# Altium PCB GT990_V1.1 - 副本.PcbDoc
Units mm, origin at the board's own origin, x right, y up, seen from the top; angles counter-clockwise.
Board outline 120.5 x 74 mm, 2 copper layers (Top Layer, Bottom Layer); 143 components, 117 nets, 494 pads, 147 vias.
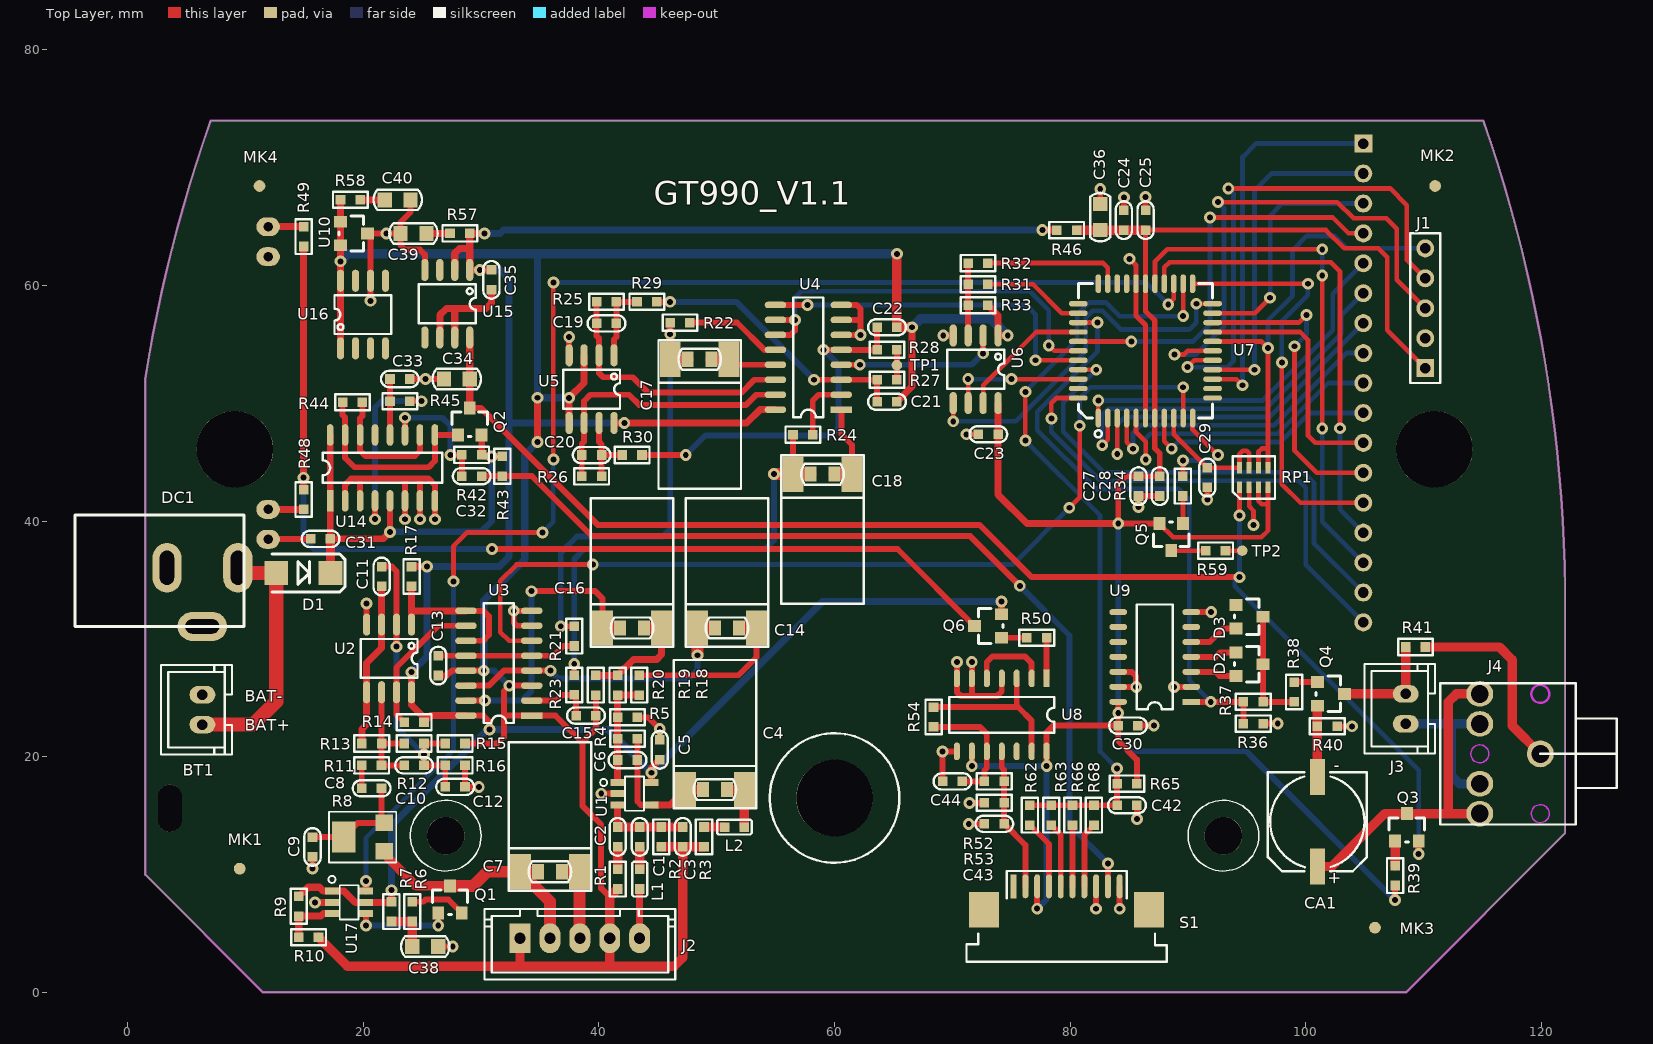
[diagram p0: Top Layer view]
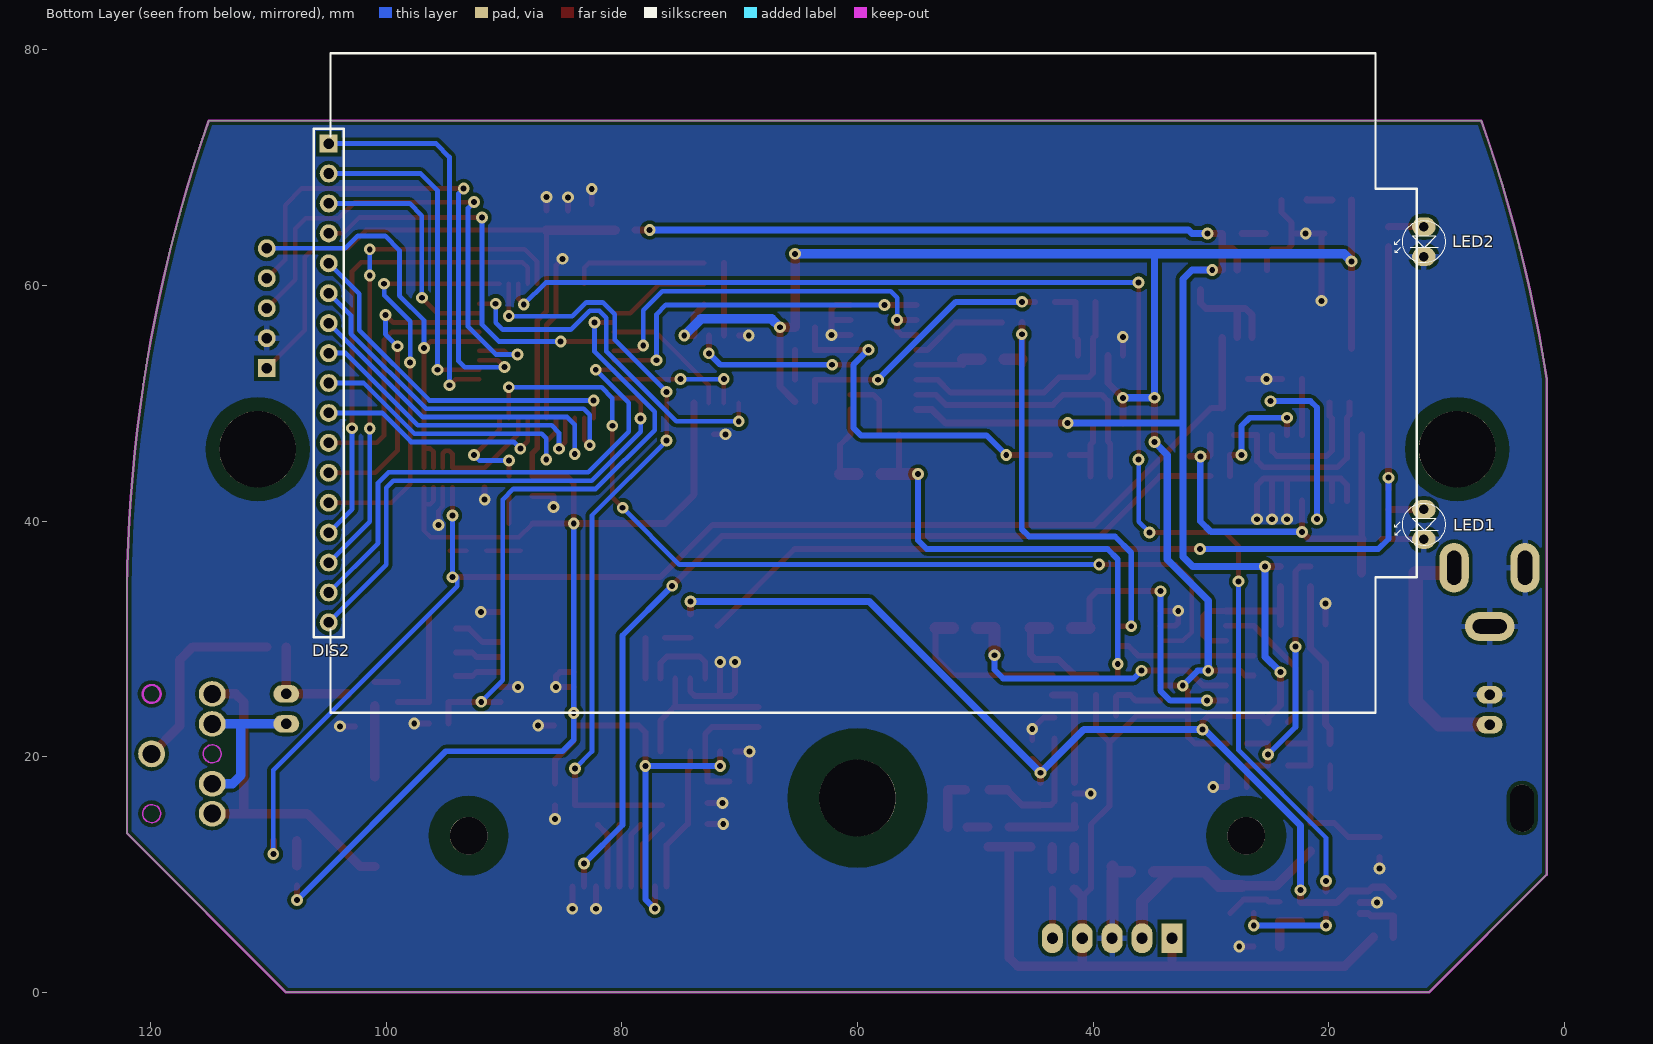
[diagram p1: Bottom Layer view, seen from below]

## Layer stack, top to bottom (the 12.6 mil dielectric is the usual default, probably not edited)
Top Solder: solder mask 0.0102, Solder Resist, Dk 3.5
Top Layer: signal copper 0.0356
Dielectric 1: dielectric 0.32, FR-4, Dk 4.8
Bottom Layer: signal copper 0.0356
Bottom Solder: solder mask 0.0102, Solder Resist, Dk 3.5

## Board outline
1.501,9.999 1.501,52.065 cw(c123.242,32.89) 7.057,73.996 7.045,74 115.06,74 115.061,74 cw(c-3.242,32.868) 122,34.303 122,13.5 108.5,0 11.5,0

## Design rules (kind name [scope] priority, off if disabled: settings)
Clearance [All] p1: gap=0.305
PolygonConnect ISVIA [ISVIA] p1: connectstyle=Direct reliefconductorwidth=0.254 reliefentries=4 polygonreliefangle="90 Angle" airgapwidth=0.254
PolygonConnect [All] p2: connectstyle=Relief reliefconductorwidth=0.5 reliefentries=4 polygonreliefangle="90 Angle" airgapwidth=0.305
RoutingVias [All] p1: holewidth=0.5 width=1.27 viastyle="Through Hole" minholewidth=0.3 minwidth=1 maxholewidth=1 maxwidth=1.27
SolderMaskExpansion [All] p1: expansion=0.102
Width [All] p1: maxlimit=1.5 minlimit=0.2 preferedwidth=0.254
30 further rules are at their usual default settings.

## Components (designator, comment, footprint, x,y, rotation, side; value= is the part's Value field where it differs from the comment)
BT1 "Battery" XH2.54-2P-D 6.349,23.993 r90 top
C1 "47nF" C0603 43.462,13.2 r270 top
C2 "1nF" C0603 41.59,13.2 r90 top
C3 "330pF" C0603 47.113,13.2 r90 top
C4 "u47J63V" CL-P5&SMD-W 49.844,17.216 r0 top
C5 "220nF" C0603 45.163,20.594 r270 top
C6 "2.2nF" C0603 42.43,19.723 r180 top
C7 "u47J63V" CL-P5&SMD-W 35.845,10.239 r0 top
C8 "220nF" C0603 20.71,17.318 r180 top
C9 "10nF" C0603 15.694,12.347 r270 top
C10 "10nF" C0603 24.314,19.268 r180 top
C11 "2.2nF" C0603 21.557,35.298 r270 top
C12 "220nF" C0603 27.799,17.44 r0 top
C13 "470nF" C0603 26.362,27.737 r90 top
C14 "1uJ63V" CL-P5&SMD-W 50.871,30.93 r0 top
C15 "470nF" C0603 38.903,23.495 r180 top
C16 "1uJ63V" CL-P5&SMD-W 42.813,30.93 r0 top
C17 "u47J63V" CL-P5&SMD-W 48.554,53.749 r180 top
C18 "u47J63V" CL-P5&SMD-W 58.978,43.99 r180 top
C19 "3.3nF" C0603 40.649,56.782 r0 top
C20 "3.3nF" C0603 39.387,45.608 r0 top
C21 "1uF" C0603 64.455,50.135 r0 top
C22 "1uF" C0603 64.455,56.451 r0 top
C23 "1uF" C0603 73.049,47.366 r180 top
C24 "220nF" C0603 84.559,65.537 r90 top
C25 "220nF" C0603 86.396,65.537 r90 top
C27 "220nF" C0603 85.799,42.967 r270 top
C28 "220nF" C0603 87.592,42.967 r270 top
C29 "220nF" C0603 91.639,43.701 r270 top
C30 "220nF" C0603 84.914,22.644 r0 top
C31 "1uF" C0603 16.378,38.489 r180 top
C32 "220nF" C0603 29.202,43.815 r180 top
C33 "220nF" C0603 23.108,52.06 r0 top
C34 "10uF/16V" C0805 27.937,52.062 r0 top
C35 "10nF" C0603 30.881,60.48 r270 top
C36 "10uF/16V" C0805 82.553,65.799 r270 top
C38 "10uF/16V" C0805 25.262,3.891 r180 top
C39 "10uF/16V" C0805 24.263,64.419 r0 top
C40 "10uF/16V" C0805 22.924,67.273 r180 top
C42 "100nF" C0603 84.822,15.88 r180 top
C43 "100nF" C0603 73.56,14.3 r180 top
C44 "100nF" C0603 70.007,17.904 r180 top
CA1 "470uF/16V" SMD-D8X10.5MM 100.98,14.485 r90 top
D1 "SS14" SMA 14.919,35.598 r0 top
D2 "BAT54A" SOT-23 95.227,27.854 r270 top
D3 "BAT54A" SOT-23 95.227,31.887 r270 top
DC1 "DC005" DC005 6.351,33.547 r180 top
DIS2 "LCD" DIP17-2.54 104.875,51.721 r270 bottom
J1 "NC" DIP5-2.54 110.134,58.067 r90 top
J2 "XH2.54-5P" XH2.54-5P-D 38.382,4.592 r0 top
J3 "XH2.54-2P" XH2.54-2P-D 108.473,24.066 r90 top
J4 "PJ-306" PJ-306 117.331,20.25 r270 top
L1 "27uH" L0603 43.462,9.611 r270 top
L2 "27uH" L0603 51.506,14.034 r180 top
LED1 "LED" LED-3MM-CLEAR 11.927,39.722 r270 bottom
LED2 "LED" LED-3MM-CLEAR 11.927,63.717 r270 bottom
MK1 "" MARK 9.509,10.503 r0 top
MK2 "" MARK 110.975,68.443 r0 top
MK3 "" MARK 105.867,5.491 r0 top
MK4 "" MARK 11.194,68.443 r0 top
Q1 "MMBT4403LT1G" SOT-23 27.361,7.89 r0 top
Q2 "ZXMP3A13FTA" SOT-23 29.038,48.465 r0 top
Q3 "FMMT591ATA" SOT-23 108.576,14.019 r0 top
Q4 "ZXMN3A01FTA" SOT-23 102.131,25.336 r270 top
Q5 "MMBT4403LT1G" SOT-23 88.57,38.646 r180 top
Q6 "S9012" SOT-23 73.018,31.102 r90 top
R1 "4.99K/1%" R0603 41.59,9.611 r90 top
R2 "30.1K/1%" R0603 45.301,13.2 r90 top
R3 "49.9R/1%" R0603 48.918,13.2 r90 top
R4 "30.1K/1%" R0603 42.43,21.539 r180 top
R5 "10K" R0603 42.43,23.348 r0 top
R6 "10R" R0603 24.163,6.852 r90 top
R7 "10R" R0603 22.394,6.853 r270 top
R8 "500R" SMD-3X3MM 20.066,13.186 r90 top
R9 "453R/1%" R0603 14.524,7.308 r90 top
R10 "499R/1%" R0603 15.363,4.674 r180 top
R11 "6.04K/1%" R0603 20.713,19.263 r0 top
R12 "28K/1%" R0603 24.314,21.123 r0 top
R13 "10K" R0603 20.718,21.123 r0 top
R14 "10K" R0603 24.314,22.926 r180 top
R15 "10K" R0603 27.799,21.123 r180 top
R16 "20K" R0603 27.799,19.268 r180 top
R17 "10K" R0603 24.097,35.298 r270 top
R18 "4.99K/1%" R0603 43.428,26.076 r90 top
R19 "40.2K/1%" R0603 41.584,26.076 r90 top
R20 "5.76K/1%" R0603 39.74,26.073 r90 top
R21 "10K" R0603 37.903,30.236 r90 top
R22 "274K/1%" R0603 46.886,56.85 r0 top
R23 "10K" R0603 37.903,26.083 r90 top
R24 "274K/1%" R0603 57.311,47.341 r0 top
R25 "2.21M/1%" R0603 40.652,58.61 r0 top
R26 "2.21M/1%" R0603 39.387,43.792 r0 top
R27 "20K" R0603 64.455,51.996 r0 top
R28 "100K" R0603 64.455,54.536 r0 top
R29 "2K" R0603 44.073,58.61 r0 top
R30 "2K" R0603 42.818,45.611 r0 top
R31 "162K/1%" R0603 72.178,60.094 r0 top
R32 "64.9K/1%" R0603 72.178,61.9 r0 top
R33 "10R" R0603 72.178,58.323 r0 top
R34 "20K" R0603 89.571,42.967 r270 top
R36 "100K" R0603 95.54,22.814 r180 top
R37 "10K" R0603 95.54,24.661 r180 top
R38 "49.9K/1%" R0603 99.002,25.499 r270 top
R39 "4.99K/1%" R0603 107.575,9.909 r90 top
R40 "0R" R0603 101.818,22.583 r0 top
R41 "274R/1%" R0603 109.308,29.314 r0 top
R42 "499K/1%" R0603 29.202,45.621 r0 top
R43 "20K" R0603 31.811,44.653 r90 top
R44 "20K" R0603 19.084,50.089 r180 top
R45 "1M" R0603 23.108,50.18 r0 top
R46 "4.99R/1%" R0603 79.703,64.699 r0 top
R48 "100R" R0603 14.934,41.831 r90 top
R49 "100R" R0603 14.934,64.148 r270 top
R50 "1K" R0603 77.164,30.104 r0 top
R52 "10K" R0603 73.557,17.907 r180 top
R53 "5.1K" R0603 73.557,16.086 r0 top
R54 "1M" R0603 68.401,23.378 r90 top
R57 "0.47R/1%" R0603 28.199,64.419 r0 top
R58 "0.47R/1%" R0603 18.908,67.27 r0 top
R59 "49.9R/1%" R0603 92.342,37.495 r180 top
R62 "4.53K/1%" R0603 76.582,15.042 r270 top
R63 "2.32K/1%" R0603 78.391,15.042 r270 top
R65 "10K" R0603 84.822,17.724 r180 top
R66 "12.7K/1%" R0603 80.197,15.042 r270 top
R68 "7.68K/1%" R0603 82.018,15.042 r270 top
RP1 "22K" RP0603 95.583,43.701 r0 top
S1 "FPC-1.0MM-10P-UP" FPC-1.0MM-10P 79.699,8 r0 top
TP1 "" TP35 65.293,53.241 r0 top
TP2 "" TP35 94.607,37.495 r90 top
U1 "TS971ILT" SOT-23-5 43.026,16.868 r270 top
U2 "LM393DR" SOP8 22.191,28.344 r180 top
U3 "74HC4053D" SOP16 31.51,27.94 r180 top
U4 "74HC4053D" SOP16 57.78,53.901 r180 top
U5 "TLC2262AIDR" SOP8 39.382,51.201 r180 top
U6 "MCP3301-CI/SN" SOP8 71.977,52.885 r180 top
U7 "PIC16F1939-I/PT" TQFP44 86.389,54.45 r0 top
U8 "MC14013BDG" SOP14 74.192,23.557 r270 top
U9 "SN74HC393DR" SOP14 87.175,28.471 r180 top
U10 "NC/TL431ACDBZR" SOT-23 19.217,64.409 r270 top
U14 "74HC4053D" SOP16 21.635,44.516 r90 top
U15 "LP2951ACMC" SOP8 27.132,58.448 r180 top
U16 "TL431ACDR" SOP8 19.974,57.532 r0 top
U17 "TS5A3157DBVR" SOT-23-6 18.798,7.64 r270 top

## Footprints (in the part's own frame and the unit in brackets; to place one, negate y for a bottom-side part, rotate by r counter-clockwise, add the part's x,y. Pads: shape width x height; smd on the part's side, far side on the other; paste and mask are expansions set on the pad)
C0603 [mil]
  rect 32x32 smd: 1(-33,0) 2(33,0)
  silkscreen extent -63,-27 63,27, body extent -31,-16 32,16, height 20
C0805 [mm]
  rect 1.2x1.27 smd: 1(-1.1,0) 2(1.1,0)
  silkscreen extent -2.06,-0.86 2.06,0.86, body extent -1,-0.62 1,0.63, height 0.8
CL-P5&SMD-W [mm]
  rect 1.778x3 smd: 1(-2.5,0) 2(2.5,0)
  rect 1.016x1.3 smd: 1(-1.016,0) 2(1.016,0)
  silkscreen extent -3.5,-1.6 3.5,11
DC005 [mil]
  oval 98x165 hole 47.24 slot 114 at 90 deg: 1(-118.5,-98) 3(118.5,-98)
  oval 165x98 hole 47.24 slot 114 at 0 deg: 2(0.5,98)
  silkscreen extent -138,-275 426,98, body extent -146,-270 420,100, height 437
DIP5-2.54 [mil]
  rect 60x60 hole 35.43: 1(-200,0)
  round 60 hole 35.43: 2(-100,0) 3(0,0) 4(100,0) 5(200,0)
  silkscreen extent -250,-50 250,50, body extent -250,-50 250,50, height 336
DIP17-2.54 [mil]
  rect 60x60 hole 35.43: 1(-800,0)
  round 60 hole 35.43: 2(-700,0) 3(-600,0) 4(-500,0) 5(-400,0) 6(-300,0) 7(-200,0) 8(-100,0) 9(0,0) 10(100,0) 11(200,0) 12(300,0) 13(400,0) 14(500,0) 15(600,0) 16(700,0) 17(800,0)
  silkscreen extent -850,-50 850,50, body extent -851,-50 850,51, height 336
FPC-1.0MM-10P [mm]
  rect 0.508x2.032 smd mask+0.025: 1(-4.5,1)
  oval 0.508x2.032 smd mask+0.025: 2(-3.5,1) 3(-2.5,1) 4(-1.5,1) 5(-0.5,1) 6(0.5,1) 7(1.5,1) 8(2.5,1) 9(3.5,1) 10(4.5,1)
  rect 2.54x3 smd mask+0.025: 11(-7,-1) 12(7,-1)
  silkscreen extent -8.5,-5.4 8.5,2.3, body extent -7.9,-5.07 7.9,1.43, height 2.7
L0603 [mm]
  rect 0.813x0.813 smd: 1(-0.838,0) 2(0.838,0)
  silkscreen extent -1.47,-0.64 1.47,0.64, body extent -0.8,-0.4 0.8,0.4, height 0.4
LED-3MM-CLEAR [mm]
  oval 1.6x2 hole 0.8: 1(-1.27,0) 2(1.27,0)
  silkscreen extent -1.8,-2.48 1.8,1.8, body extent -1.9,-1.9 1.53,1.9, height 10.64
MARK [mm]
  round 1 smd mask+1: 1(0,0)
  Top Layer pour cut-out: -1.5,0 -1.351,-0.651 -0.935,-1.173 -0.334,-1.462 0.334,-1.462 0.935,-1.173 1.351,-0.651 1.5,0 1.5,0 1.5,-0.003 1.351,0.648 0.935,1.17 0.334,1.46 -0.334,1.46 -0.935,1.17 -1.351,0.648 -1.5,-0.003 -1.5,-0.003
PJ-306 [mil]
  round 90 hole 60 mask+4: 1(0,101.15)
  oval 85x90 hole 60 mask+4: 2(200,-101.15) 3(100,-101.15) 4(-100,-101.15) 5(-200,-101.15)
  Keep-Out Layer circle w5: c200,101.15 r30
  Keep-Out Layer circle w7.87: c-200,101.15 r30
  Keep-Out Layer circle w5: c0,-101.15 r30
  silkscreen extent -236,-233 236,357, body extent -236,-240 236,354, height 394
R0603 [mil]
  rect 32x32 smd: 1(-33,0) 2(33,0)
  silkscreen extent -58,-27 58,27, body extent -31,-16 32,16, height 18
RP0603 [mil]
  rect 17x38 smd: 1(-47.5,-33) 2(-15.5,-33) 3(15.5,-33) 4(47.5,-32.99) 5(47.5,32.99) 6(15.5,33) 7(-15.5,33) 8(-47.5,32.99)
  silkscreen extent -71,-71 71,71, body extent -63,-31 63,31, height 20
SMA [mm]
  rect 2x2 smd: 1(-2.3,0) 2(2.3,0)
  silkscreen extent -2.68,-1.6 3.55,1.6, body extent -2.3,-1.35 2.3,1.35, height 2.4
SMD-3X3MM [mm]
  rect 1.4x1.5 smd: 1(-1.199,-1.725) 2(1.199,-1.724)
  rect 2.6x2 smd: 3(-0.001,1.725)
  silkscreen extent -2.15,-2.73 2.15,2.97, body extent -1.9,-2.11 1.9,2.39, height 1.01
SMD-D8X10.5MM [mm]
  rect 3.048x1.27 smd mask+0.025: 1(-3.8,0) 2(3.8,0)
  silkscreen extent -4.2,-4.2 4.2,4.2, body extent -4.95,-4.15 4.95,4.15, height 10.2
SOP8 [mil]
  oval 24x74 smd: 1(-75,-113) 2(-25,-113) 3(25,-113) 4(75,-113) 5(75,113) 6(25,113) 7(-25,113) 8(-75,113)
  silkscreen extent -95,-65 95,65, body extent -96,-118 96,118, height 67
SOP14 [mm]
  rect 1.5x0.51 smd: 1(-3.1,3.81)
  oval 1.5x0.51 smd: 2(-3.1,2.54) 3(-3.1,1.27) 4(-3.1,0) 5(-3.1,-1.27) 6(-3.1,-2.54) 7(-3.1,-3.81) 8(3.1,-3.81) 9(3.1,-2.54) 10(3.1,-1.27) 11(3.1,0) 12(3.1,1.27) 13(3.1,2.54) 14(3.1,3.81)
  silkscreen extent -1.52,-4.44 1.52,4.44, body extent -3.1,-4.35 3.1,4.35, height 1.61
SOP16 [mil]
  rect 72x22 smd: 1(-110,175)
  oval 72x22 smd: 2(-110,125) 3(-110,75) 4(-110,25) 5(-110,-25) 6(-110,-75) 7(-110,-125) 8(-110,-175) 9(110,-175) 10(110,-125) 11(110,-75) 12(110,-25) 13(110,25) 14(110,75) 15(110,125) 16(110,175)
  silkscreen extent -50,-200 50,200, body extent -123,-196 123,196, height 62
SOT-23 [mm]
  rect 1x1.1 smd: 1(-1,-1.15) 2(1,-1.15) 3(0,1.15)
  silkscreen extent -1.5,-1.27 1.5,0.8, body extent -1.45,-1.4 1.45,1.4, height 1.2
SOT-23-5 [mm]
  rect 0.6x1.2 smd: 1(-0.95,-1.435) 2(0,-1.435) 3(0.95,-1.435) 4(0.95,1.435) 5(-0.95,1.435)
  silkscreen extent -1.45,-2.93 1.45,0.8, body extent -1.45,-1.4 1.45,1.4, height 1.2
SOT-23-6 [mm]
  rect 0.6x1.2 smd: 1(-0.95,-1.435) 2(0,-1.435) 3(0.95,-1.435) 4(0.95,1.435) 5(0,1.435) 6(-0.95,1.435)
  silkscreen extent -2.25,-1.75 1.45,0.8, body extent -1.5,-1.4 1.5,1.4, height 0.86
TP35 [mil]
  round 35 smd: 1(0,0)
TQFP44 [mm]
  oval 0.457x1.6 smd mask+0.025: 1(-4,-5.7) 2(-3.2,-5.7) 3(-2.4,-5.7) 4(-1.6,-5.7) 5(-0.8,-5.7) 6(0,-5.7) 7(0.8,-5.7) 8(1.6,-5.7) 9(2.4,-5.7) 10(3.2,-5.7) 11(4,-5.7) 23(4,5.7) 24(3.2,5.7) 25(2.4,5.7) 26(1.6,5.7) 27(0.8,5.7) 28(0,5.7) 29(-0.8,5.7) 30(-1.6,5.7) 31(-2.4,5.7) 32(-3.2,5.7) 33(-4,5.7)
  oval 1.6x0.457 smd mask+0.025: 12(5.7,-4) 13(5.7,-3.2) 14(5.7,-2.4) 15(5.7,-1.6) 16(5.7,-0.8) 17(5.7,0) 18(5.7,0.8) 19(5.7,1.6) 20(5.7,2.4) 21(5.7,3.2) 22(5.7,4) 34(-5.7,4) 35(-5.7,3.2) 36(-5.7,2.4) 37(-5.7,1.6) 38(-5.7,0.8) 39(-5.7,0) 40(-5.7,-0.8) 41(-5.7,-1.6) 42(-5.7,-2.4) 43(-5.7,-3.2) 44(-5.7,-4)
  silkscreen extent -5.7,-7.34 5.7,5.7, body extent -6.01,-6.01 6.01,6.01, height 1.1
XH2.54-2P-D [mm]
  oval 1.5x2.2 hole 0.9: 1(-1.27,0) 2(1.27,0)
  silkscreen extent -3.8,-2.5 3.8,3.5, body extent -3.7,-2.76 3.7,3.34, height 7
XH2.54-5P-D [mil]
  rect 70x100 hole 37: 1(-200,0)
  oval 70x100 hole 37: 2(-100,0) 3(0,0) 4(100,0) 5(200,0)
  silkscreen extent -318,-138 319,98, body extent -293,-134 293,93, height 276

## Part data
BT1 J3: library part XH2.54-2P-D, "XH-2A 2脚直插 脚距2.5mm"
C1: library part C-47nF-0603, "47nF(473) K 0603"
C2: library part C-1nF-0603, "1nF(102) K 0603 50V"
C3: library part C-330pF-0603, "330pF(331) K 0603"
C4 C7 C17 C18: library part C-470nF-63V-PF, "470nF（474）5% 100V 脚距5mm"
C5 C8 C12 C24 C25 C27 C28 C29 C30 C32 C33: library part C-220nF-0603, "220nF(224) K 0603 25V"
C6 C11: library part C-2.2nF-0603, "2.2nF(222) K 0603"
C9 C10 C35: library part C-10nF-0603, "10nF(103) K 0603"
C13 C15: library part C-470nF-0603, "470nF(474) K 0603 25V"
C14 C16: library part C-1uF-63V-PF, "1uF（105）5% 100V 脚距5mm"
C19 C20: library part C-3.3nF-0603, "3.3nF(332) K 0603"
C21 C22 C23 C31: library part C-1uF-0603, "1uF(105) K 0603 25V"
C34 C36 C38 C39 C40: library part C-10uF-0805-16V, "10uF(106) K 0805 16V"
C42 C43 C44: library part C-100nF-0603, "100nF(104) K 0603"
CA1: library part C-470uF-16V-D8XL10.5MM, "470uF/16V Φ8×10.5"
D1: "SS14 SMA"
D2 D3: "BAT54A SOT-23"
DC1: "DC-005 2mm针全铜"
DIS2: library part "17 HEADER", "显示屏"
J1: library part XH2.54-5P-D
J2: library part XH2.54-5P-D, "XH-4A 5脚直插 脚距2.5mm"
J4: "5脚 PJ-306全铜 双声道3.5mm音频"
L1 L2: library part L-27uH-0603, "27uH 0603"
LED1 LED2: "背光"
MK1 MK2 MK3 MK4: library part MARK, "NC"
Q1 Q5: "MMBT4403LT1G SOT-23"
Q2: "ZXMP3A13FTA SOT-23"
Q3: "FMMT591ATA SOT-23(代号591)"
Q4: "ZXMN3A01FTA SOT-23"
Q6: "S9012 SOT-23（代号2T1）"
R1 R18 R39: library part R-4.99K-0603-1%, "1/16W 1% 4.99KΩ 0603"
R2 R4: library part R-30.1K-0603-1%, "1/16W 1% 30.1KΩ 0603"
R3 R59: library part R-49.9R-0603-1%, "1/16W 1% 49.9Ω 0603"
R5 R13 R14 R15 R17 R21 R23 R37 R52 R65: library part R-10K-0603, "1/16W 5% 10KΩ 0603"
R6 R7 R33: library part R-10R-0603-1%, "1/16W 1% 10Ω 0603"
R8: library part R-500R-SMD-3X3MM, "500Ω 3X3"
R9: library part R-453R-0603-1%, "1/16W 1% 453Ω 0603"
R10: library part R-499R-0603-1%, "1/16W 1% 499Ω 0603"
R11: library part R-6.04K-0603-1%, "1/16W 1% 6.04KΩ 0603"
R12: library part R-28K-0603-1%, "1/16W 1% 28KΩ 0603"
R16 R27 R34 R43 R44: library part R-20K-0603, "1/16W 5% 20KΩ 0603"
R19: library part R-40.2K-0603-1%, "1/16W 1% 40.2KΩ 0603"
R20: library part R-5.76K-0603-1%, "1/16W 1% 5.76KΩ 0603"
R22 R24: library part R-274K-0603-1%, "1/16W 1% 274KΩ 0603"
R25 R26: library part R-2.21M-0603-1%, "1/16W 1% 2.21MΩ 0603"
R28 R36: library part R-100K-0603, "1/16W 5% 100KΩ 0603"
R29 R30: library part R-2K-0603, "1/16W 5% 2KΩ 0603"
R31: library part R-162K-0603-1%, "1/16W 1% 162KΩ 0603"
R32: library part R-64.9K-0603-1%, "1/16W 1% 64.9KΩ 0603"
R38: library part R-49.9K-0603-1%, "1/16W 1% 49.9KΩ 0603"
R40: library part R-0R-0603, "1/16W 5% 0Ω 0603"
R41: library part R-274R-0603-1%, "1/16W 1% 274Ω 0603"
R42: library part R-499K-0603-1%, "1/16W 1% 499KΩ 0603"
R45 R54: library part R-1M-0603, "1/16W 5% 1MΩ 0603"
R46: library part R-4.99R-0603-1%, "1/16W 1% 4.99Ω 0603"
R48 R49: library part R-100R-0603, "1/16W 5% 100Ω 0603"
R50: library part R-1K-0603, "1/16W 5% 1KΩ 0603"
R53: library part R-5.1K-0603, "1/16W 5% 5.1KΩ 0603"
R57 R58: library part R-0.47R-0603-1%, "1/16W 1% 0.47Ω 0603"
R62: library part R-4.53K-0603-1%, "1/16W 1% 4.53KΩ 0603"
R63: library part R-2.32K-0603-1%, "1/16W 1% 2.32KΩ 0603"
R66: library part R-12.7K-0603-1%, "1/16W 1% 12.7KΩ 0603"
R68: library part R-7.68K-0603-1%, "1/16W 1% 7.68KΩ 0603"
RP1: library part R-22K-0603X4, "1/16W 5% 22kΩ 4*0603"
S1: "1.0mm间距抽拉上接 1.0-10P"
TP1 TP2: library part VSRC2, "Voltage Source"
U1: "TS971ILT SOT-23-5"
U2: "LM393DR SOP8"
U3 U4 U14: "74HC4053D SOP16"
U5: "TLC2262AIDR SOP8"
U6: "MCP3301-CI/SN SOP8"
U7: "PIC16F1939-I/PT SOP28"
U8: library part MC14013B, "MC14013BDG SOP14"
U9: "SN74HC393DR SOP14"
U10: library part TL431ACDBZR, "NC"
U15: "LP2951ACMC SOP8"
U16: "TL431ACDR SOP8"
U17: "TS5A3157DBVR SOT-23-6"

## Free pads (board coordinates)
  oval 2x4 hole 2 slot 4 at 90 deg unplated: 1(3.584,15.634)
  round 6.5 hole 6.5 unplated: 1(9.1,46.1) 2(110.9,46.1) 3(60,16.5)
  round 3.2 hole 3.2 unplated: 4(27,13.3) 5(93,13.3)

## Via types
v1: diameter 1, hole 0.5, Top Layer to Bottom Layer, tented both sides, 147 vias

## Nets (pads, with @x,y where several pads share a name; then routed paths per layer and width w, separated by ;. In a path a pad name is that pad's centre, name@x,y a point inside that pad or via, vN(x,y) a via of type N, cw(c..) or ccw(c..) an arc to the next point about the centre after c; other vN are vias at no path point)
BAT: C31.1 D1.2 Q2.2 R42.2 R43.2 U14.1 U14.5 U14.16 | length 37.7
  Top Layer w0.55: U14.16 U14.1 17.19,38.515 C31.1 21.676,38.489 v1(22.27,39.082) U14.5 ; Q2.2 30.038,45.624 R42.2 30.17,45.491 v1(30.894,45.491) R43.2
  Top Layer w0.8: C31.1 17.219,38.486 D1.2
  Bottom Layer w0.55: v1(22.27,39.082) 22.272,39.079 29.988,39.079 30.894,39.985 v1(30.894,45.491)
CLK: J1.4 U7.16 | length 43.9
  Top Layer w0.4: v1(89.967,53.068) 90.549,53.65 U7.16 ; v1@93.422,68.234 107.155,68.234 108.572,66.817 108.572,62.169 J1.4
  Bottom Layer w0.4: v1(89.967,53.068) 93.335,53.068 93.853,53.586 93.853,67.803 v1(93.421,68.235)
DAT: J1.3 U7.17 | length 43.2
  Top Layer w0.4: v1(88.844,54.145) 89.682,54.145 89.987,54.45 U7.17 ; v1(92.537,67.074) 102.671,67.074 104.051,65.694 106.838,65.694 107.714,64.818 107.714,60.488 J1.3
  Bottom Layer w0.4: v1(88.844,54.145) 90.701,54.145 93.045,56.49 93.045,66.566 v1(92.537,67.074)
DOWN: R63.2 S1.5 | length 5.5
  Top Layer w0.5: R63.2 79.199,13.396 S1.5
GND: BT1.2 C5.1 C7.2 C9.2 C12.2 C23.2 C24.2 C25.2 C27.2 C28.2 C29.2 C30.2 C31.2 C33.2 C34.1 C36.1 C38.1 C39.1 C40.1 C42.1 C43.2 C44.2 DC1.2 DC1.3 J1.2 J2.3 LED1.2 LED2.2 R5.2 R16.1 R36.1 R40.2 R53.1 RP1.2 S1.8 S1.10 U1.2 U2.4 U3.7 U3.8 U4.6 U4.7 U4.8 U5.4 U6.4 U7.6 U7.29 U8.4 U8.6 U8.7 U8.8 U9.2 U9.7 U9.12 U9.13 U10.3 U14.2 U14.3 U14.6 U14.7 U14.8 U15.4 U16.6 U17.2 | length 137.1
  Top Layer w0.4: RP1.2 95.189,41.255 95.557,40.886 v1(95.557,39.672)
  Top Layer w0.45: v1(71.204,47.366) C23.2 ; v1(85.044,62.258) 85.589,61.713 U7.29 85.589,57.43 86.389,56.63 U7.6
  Top Layer w0.5: LED1.2 11.963,38.489 C31.2 ; v1(15.694,10.512) C9.2 ; U14.2 18.46,43.09 18.971,43.602 19.69,43.602 ; U14.3 19.73,43.562 19.69,43.602 ; U2.4 v1(20.286,33.011) ; v1(20.609,58.694) U16.6 20.609,64.167 U10.3 v1(21.958,64.409) C39.1@23.153,64.409 ; v1(23.54,40.159) U14.6 23.54,43.6 23.538,43.602 ; C33.2 v1(25.293,52.06) 26.835,52.06 C34.1 ; C40.1 24.024,66.228 23.153,65.358 C39.1@23.153,64.409 ; v1(24.81,40.159) U14.7 24.81,43.59 24.821,43.602 ; U15.4 25.227,62.614 24.803,63.038 23.538,63.038 23.153,63.423 C39.1@23.153,64.409 ; v1(26.08,40.159) U14.8 26.08,43.069 25.547,43.602 24.821,43.602 ; C38.1 v1(27.592,3.891) ; R16.1 C12.2 v1(29.807,17.44) ; U3.7 33.035,31.115 32.774,31.377 v1(32.774,32.385) U3.8 ; U5.4 v1(37.477,55.622) ; v1(40.201,16.868) U1.2 ; R5.2 44.163,23.348 v1(45.163,22.348) C5.1 ; U4.6 v1(62.21,55.806) 62.21,57.074 ; U4.7 62.207,57.076 62.21,57.074 ; U4.8 61.879,58.346 62.21,58.016 62.21,57.074 ; C44.2 v1(69.169,20.457) U8.8 ; v1(69.223,55.756) U6.4 ; v1(70.382,28.043) U8.7 70.382,25.482 70.698,25.166 71.636,25.166 ; v1(71.387,14.3) C43.2 ; v1(71.455,16.086) R53.1 ; v1(71.652,28.043) U8.6 71.652,25.183 71.636,25.166 ; U8.4 74.192,25.544 73.815,25.166 71.636,25.166 ; v1(82.199,7.102) S1.8 ; C36.1 v1(82.553,68.196) ; U9.13 v1(85.601,25.931) 85.601,26.833 85.232,27.201 U9.12 ; v1(84.199,7.102) S1.10 ; C24.2 v1(84.559,67.478) ; v1(85.66,14.713) C42.1 ; C30.2 v1(87.097,22.644) ; v1(85.799,41.206) C27.2 C28.2 ; C25.2 v1(86.396,67.508) ; v1(88.803,25.931) U9.2 ; U9.7 v1(91.966,32.281) ; v1(91.639,41.825) C29.2 ; R36.1 v1(97.615,22.814) ; R40.2 v1(103.916,22.583) ; 19.69,43.602 23.538,43.602 ; 23.538,43.602 24.821,43.602
  Top Layer w0.6: v1(15.9,7.64) U17.2
  Top Layer w1: C7.2@36.861,10.239 38.345,10.239 38.345,4.629 J2.3 ; C7.2@38.344,10.696 C7.2@38.382,10.658
"LED BACKLIGHT": C43.1 R52.1 R53.2 S1.2 U8.11 | length 12.3
  Top Layer w0.5: U8.11 74.192,19.079 74.395,18.876 R52.1 R53.2 74.398,16.083 C43.1 76.199,12.499 S1.2
NetC1_1: C1.1 C2.2 C3.2 R2.2 U1.3 | length 7.4
  Top Layer w0.6: C2.2 U1.3 U1.3
  Top Layer w0.8: C2.2 43.462,14.039 45.301,14.038 C3.2
NetC1_2: C1.2 L1.1 | length 1.9
  Top Layer w0.8: L1.1 C1.2
NetC2_1: C2.1 R1.2 | length 1.9
  Top Layer w0.8: R1.2 C2.1
NetC4_1: C4.1 C6.1 R4.1 U1.4 | length 11.6
  Top Layer w0.5: R4.1 C6.1 43.268,16.206 43.556,15.918 U1.4
  Top Layer w0.6: U1.4 46.047,15.918 C4.1@47.344,17.216
  Top Layer w0.8: C4.1@47.344,17.216 C4.1@48.828,17.216
NetC4_2: C4.2 L2.1 | length 4.7
  Top Layer w0.8: C4.2@50.86,17.216 C4.2@52.344,17.216 ; L2.1 C4.2@52.344,17.216
NetC6_2: C6.2 R4.2 R5.1 R18.1 R19.1 U1.1 | length 9.3
  Top Layer w0.6: U1.1 C6.2 R4.2 R5.1 41.591,25.23 R19.1 R18.1
NetC7_1: C7.1 J2.2 Q1.3 R8.1 | length 21.7
  Top Layer w0.8: R8.1@21.548,11.979 24.487,9.04 Q1.3
  Top Layer w1: Q1.3 29.342,9.04 30.541,10.239 C7.1@33.345,10.239 ; C7.1@34.829,10.239 C7.1@33.345,10.239 ; J2.2 35.842,7.742 C7.1@33.345,10.239
NetC8_1: C8.1 C9.1 R8.2 R8.3 | length 9.3
  Top Layer w0.5: C9.1 R8.3 19.535,14.379 21.548,14.379 C8.1
NetC8_2: C8.2 R11.1 | length 1.9
  Top Layer w0.5: C8.2 19.872,19.261 R11.1
NetC10_1: C10.1 C11.1 C12.1 R12.2 R15.2 R16.2 U2.2 | length 25.2
  Top Layer w0.5: C11.1 22.424,36.136 22.826,35.734 U2.2 v1(22.826,29.343) ; C12.1 R16.2 C10.1 R12.2 R15.2@26.96,21.123
  Bottom Layer w0.5: v1(22.826,29.343) 22.826,22.523 v1(25.154,20.196)
NetC10_2: C10.2 R11.2 R12.1 R13.2 U2.6 | length 10.1
  Top Layer w0.5: U2.6 R13.2 ; C10.2 21.556,19.268 R11.2 21.551,21.118 R13.2 ; R12.1 R13.2
NetC11_2: C11.2 R13.1 U2.3 U2.5 | length 14
  Top Layer w0.6: R13.1 19.879,22.348 20.286,22.755 U2.5 20.286,27.964 21.556,29.234 U2.3 C11.2 C11.2
NetC13_2: C13.2 R21.1 U3.5 U3.12 | length 11.9
  Top Layer w0.5: C13.2 U3.12 U3.5 36.167,28.575 36.99,29.398 R21.1
NetC14_1: C14.1 U3.4 U3.14 | length 25.8
  Top Layer w0.5: U3.14 30.66,26.035 31.93,27.305 U3.4 v1(35.898,27.305)
  Top Layer w1: v1(48.371,28.616) 48.371,30.93 C14.1@49.855,30.93
  Bottom Layer w0.5: v1(35.898,27.305) 36.556,26.647 47.638,26.647 48.371,27.381 v1(48.371,28.616)
  Bottom Layer w1: v1(48.371,28.616) v1@48.387,28.6
NetC14_2: C14.2 R18.2 | length 14.5
  Top Layer w0.5: R18.2 51.844,26.914 53.371,28.441 C14.2@53.371,30.93
  Top Layer w1: C14.2@51.887,30.93 C14.2@53.371,30.93
NetC15_2: C15.2 R23.1 U3.2 | length 5.6
  Top Layer w0.5: U3.2 36.386,24.765 36.866,25.245 R23.1 38.064,25.084 C15.2
NetC16_1: C16.1 U3.15 | length 24.6
  Top Layer w0.5: U3.15 v1(30.33,24.765) ; v1(34.287,34.051) 39.68,34.051 40.313,33.418 C16.1@40.313,30.93
  Top Layer w1: C16.1@40.313,30.93 C16.1@41.797,30.93
  Bottom Layer w0.5: v1(30.33,24.765) 33.439,24.765 34.287,25.613 v1(34.287,34.051)
NetC16_2: C16.2 R19.2 R20.2 | length 10
  Top Layer w0.6: R20.2 39.742,26.914 R19.2 42.93,28.26 44.91,28.26 45.313,28.663 C16.2@45.313,30.93
  Top Layer w1: C16.2@43.829,30.93 C16.2@45.313,30.93
NetC17_1: C17.1 U4.13 | length 5.4
  Top Layer w0.5: C17.1@51.052,53.264 51.054,53.266 U4.13
  Top Layer w1: C17.1@49.568,53.746 C17.1@51.052,53.746
NetC17_2: C17.2 R21.2 R22.1 | length 38.6
  Top Layer w0.5: v1(36.761,31.074) R21.2
  Top Layer w0.6: C17.2@46.048,53.268 C17.2@46.052,53.264 ; C17.2@46.048,53.75 v1(46.048,55.86) R22.1
  Top Layer w1: C17.2@46.052,53.746 C17.2@47.536,53.746
  Bottom Layer w0.5: v1(36.761,31.074) 36.761,37.318 38.136,38.692 45.43,38.692 46.052,39.313 46.052,55.856 v1(46.048,55.86)
NetC18_1: C18.1 U4.1 | length 7.3
  Top Layer w0.5: U4.1 60.574,47.368 61.478,46.465 C18.1@61.478,43.99
  Top Layer w1: C18.1@59.994,43.99 C18.1@61.478,43.99
NetC18_2: C18.2 R23.2 R24.1 | length 39.5
  Top Layer w0.5: R23.2 v1(37.903,27.863) ; R24.1 56.478,47.335 C18.2@56.478,43.99
  Top Layer w1: v1(54.856,43.99) 56.478,43.99 C18.2@57.962,43.99
  Bottom Layer w0.5: v1(37.903,27.863) 37.903,36.768 38.773,37.638 54.115,37.638 54.856,38.379 v1(54.856,43.99)
NetC19_1: C19.1 R25.1 U4.14 U5.2 | length 22.2
  Top Layer w0.5: R25.1 39.811,58.608 C19.1 39.811,55.713 40.017,55.508 U5.2 40.017,52.551 40.361,52.207 42.88,52.207 44.181,50.907 52.095,50.907 53.185,51.996 U4.14
NetC19_2: C19.2 R25.2 R29.1 U5.1 | length 6.4
  Top Layer w0.5: U5.1 41.287,55.424 41.487,55.625 C19.2 41.487,58.608 R25.2 R29.1
NetC20_1: C20.1 R26.1 U4.15 U5.6 | length 23.7
  Top Layer w0.5: R26.1 C20.1 38.548,46.555 38.747,46.753 U5.6 38.747,50.197 39.276,50.726 42.558,50.726 43.416,49.868 52.497,49.868 53.355,50.726 U4.15
NetC20_2: C20.2 R26.2 R30.1 U5.7 | length 6.4
  Top Layer w0.5: U5.7 40.017,46.724 40.225,46.516 C20.2 ; R26.2 C20.2 ; R30.1 41.977,45.608 C20.2
NetC21_1: C21.1 R27.1 R29.2 U4.3 | length 23.3
  Top Layer w0.5: R29.2 v1(46.027,58.61) ; v1(58.265,51.996) U4.3 R27.1 C21.1@63.617,50.135
  Bottom Layer w0.5: v1(46.027,58.61) 51.651,58.61 v1(58.265,51.996)
NetC22_1: C22.1 R28.1 R30.2 U4.5 | length 31.3
  Top Layer w0.5: R30.2 v1(47.374,45.611) ; v1(59.07,54.536) U4.5 R28.1 C22.1
  Bottom Layer w0.5: v1(47.374,45.611) 49.042,47.28 59.71,47.28 60.345,47.915 60.345,53.261 v1(59.07,54.536)
NetC29_1: C29.1 RP1.7 RP1.8 U7.9 | length 11.5
  Top Layer w0.4: U7.9 88.789,47.389 C29.1 RP1.8 94.376,45.72 94.635,45.979 94.971,45.979 95.189,45.761 RP1.7
NetC32_2: C32.2 R42.1 U14.11 | length 10.8
  Top Layer w0.5: U14.11 v1(23.54,48.774) ; v1(27.407,45.621) R42.1 C32.2
  Bottom Layer w0.5: v1(23.54,48.774) 26.717,48.774 27.407,48.085 v1(27.407,45.621)
NetC33_1: C33.1 R45.1 U14.12 | length 4.7
  Top Layer w0.5: U14.12 R45.1 C33.1
NetC35_2: C35.2 U15.6 U15.7 | length 10.3
  Top Layer w0.6: U15.6 26.497,57.48 27.056,58.039 27.849,58.039 ; U15.7 27.767,57.958 27.849,58.039 ; C35.2 30.881,58.517 30.404,58.039 27.849,58.039
NetC38_2: C38.2 R6.1 R7.2 | length 3.9
  Top Layer w0.8: R7.2 R6.1 ; C38.2 24.163,3.892 R6.1
NetC39_2: C39.2 R57.1 | length 2
  Top Layer w0.6: C39.2 R57.1
NetC40_2: C40.2 R58.2 | length 2.1
  Top Layer w0.6: R58.2 21.821,67.27 C40.2
NetC44_1: C44.1 R52.2 R54.1 U8.10 | length 10.8
  Top Layer w0.5: R54.1 72.334,22.54 72.922,21.952 U8.10 72.922,19.041 72.719,18.838 R52.2 72.717,17.904 C44.1
NetCA1_1: CA1.1 J4.2 J4.5 Q3.3 | length 28.1
  Top Layer w0.8: CA1.1 102.199,10.685 106.683,15.169 Q3.3 108.577,15.17 112.093,15.17 ; J4.2 112.093,15.17 ; J4.5 112.777,25.33 112.093,24.646 112.093,15.17
NetCA1_2: CA1.2 Q4.2 R40.1 | length 6.1
  Top Layer w0.8: CA1.2 R40.1 ; R40.1@100.981,22.584 Q4.2
NetD2_1: D2.1 U9.4 | length 4
  Top Layer w0.5: U9.4 92.321,28.471 92.704,28.854 D2.1
NetD2_2: D2.2 U9.3 | length 3.9
  Top Layer w0.5: U9.3 92.326,27.201 92.674,26.854 D2.2
NetD2_3: D2.3 D3.3 R37.1 R38.2 | length 9.9
  Top Layer w0.5: D2.3@96.377,27.854 D3.3 ; D2.3 96.377,24.661 R38.2
NetD3_2: D3.2 U9.5 | length 4.3
  Top Layer w0.5: U9.5 91.839,29.741 92.985,30.887 D3.2
NetJ2_5: J2.5 L1.2 | length 4.2
  Top Layer w0.6: J2.5 L1.2
NetJ3_1: J3.1 J4.3 J4.4 | length 13.4
  Bottom Layer w0.8: J3.1 114.755,22.796 J4.4 ; 112.324,22.789 112.324,18.428 113.042,17.71 J4.3
NetJ3_2: J3.2 Q4.3 R41.1 | length 9.2
  Top Layer w0.8: Q4.3 J3.2 108.473,29.31 R41.1
NetJ4_1: J4.1 R41.2 | length 16.8
  Top Layer w0.8: R41.2 116.426,29.314 117.511,28.23 117.511,22.639 J4.1
NetL2_2: L2.2 R3.2 | length 1.8
  Top Layer w0.8: R3.2 50.663,14.039 L2.2
NetLED1_1: LED1.1 R48.1 | length 3
  Top Layer w0.6: LED1.1 R48.1 R48.1
NetLED2_1: LED2.1 R49.1 | length 3
  Top Layer w0.6: LED2.1 14.932,64.987 R49.1
NetQ1_1: Q1.1 U17.4 | length 8.2
  Top Layer w0.5: v1(20.233,5.669) U17.4 ; v1(26.36,5.669) Q1.1@26.36,6.739
  Bottom Layer w0.5: v1(20.233,5.669) v1(26.36,5.669)
NetQ1_2: Q1.2 R6.2 | length 4.7
  Top Layer w0.5: R6.2 25.112,7.69 25.291,7.869 27.232,7.869 Q1.2
NetQ2_1: Q2.1 R44.2 U14.9 U14.15 | length 17.1
  Top Layer w0.5: R44.2 18.246,49.008 18.46,48.795 U14.15 18.46,45.363 19.251,44.572 25.547,44.572 26.08,45.104 U14.9 26.085,47.315 Q2.1
NetQ3_1: Q3.1 R39.2 | length 2.1
  Top Layer w0.8: R39.2 Q3.1
NetQ4_1: Q4.1 R38.1 | length 2
  Top Layer w0.5: R38.1 Q4.1
NetQ5_1: Q5.1 R34.2 | length 2.3
  Top Layer w0.4: Q5.1 R34.2
NetQ5_3: Q5.3 R59.2 | length 2.9
  Top Layer w0.4: Q5.3 R59.2
NetQ6_1: Q6.1 R50.1 | length 2.2
  Top Layer w0.5: Q6.1 74.171,30.104 R50.1
NetQ6_3: Q6.3 R48.2 R49.2 | length 85.8
  Top Layer w0.5: v1(30.917,37.628) 65.342,37.628 Q6.3
  Top Layer w0.6: R48.2 R49.2
  Bottom Layer w0.5: v1(14.935,43.685) 14.935,38.489 15.796,37.628 v1(30.917,37.628)
NetR9_1: R9.1 R10.2 U17.3 | length 4.7
  Top Layer w0.6: R10.2 14.525,6.468 R9.1 16.406,6.469 16.627,6.69 U17.3
NetR14_2: R14.2 U2.7 U3.10 | length 12.3
  Top Layer w0.5: R14.2 22.826,23.576 U2.7 22.826,27.583 26.358,31.115 U3.10
NetR17_2: R17.2 U2.1 U3.9 U3.11 | length 13.7
  Top Layer w0.5: U3.11 30.175,29.845 30.658,30.328 30.658,31.923 30.196,32.385 U3.9
  Top Layer w0.6: U2.1 24.096,32.393 ; R17.2 R17.2 24.096,32.393 ; U3.9 24.103,32.385 24.096,32.393
NetR22_2: R22.2 U4.12 | length 8.2
  Top Layer w0.5: R22.2 51.727,56.85 54.041,54.536 U4.12
NetR24_2: R24.2 U4.2 | length 5.5
  Top Layer w0.5: R24.2 58.149,50.237 58.638,50.726 U4.2
NetR27_2: R27.2 R28.2 TP1.1 | length 2.5
  Top Layer w0.5: R27.2 TP1.1 R28.2
NetR31_1: R31.1 R32.1 R33.1 U6.3 | length 6.1
  Top Layer w0.5: R32.1 R31.1 R33.1 71.342,58.321 U6.3
NetR34_1: R34.1 U7.11 | length 8.5
  Top Layer w0.4: R34.1 v1(89.571,45.143) ; U7.11 90.389,47.754 v1(92.54,45.603)
  Bottom Layer w0.4: v1(89.571,45.143) 92.08,45.143 v1(92.54,45.603)
NetR44_1: R44.1 U14.10 U14.14 | length 11
  Top Layer w0.5: R44.1 19.923,48.927 19.73,48.734 U14.14 19.73,45.975 20.18,45.524 24.384,45.524 24.81,45.95 U14.10
NetR45_2: R45.2 U14.4 | length 16.2
  Top Layer w0.5: v1(21,40.164) U14.4 ; R45.2 v1(24.943,50.18)
  Bottom Layer w0.5: v1(21,40.164) 21,49.636 21.544,50.18 v1(24.943,50.18)
NetR50_2: R50.2 U8.1 | length 3.4
  Top Layer w0.5: U8.1 R50.2
NetR54_2: R54.2 U8.3 U8.13 | length 13.9
  Top Layer w0.5: R54.2 75.575,24.216 ; U8.3 75.462,24.329 75.575,24.216 ; U8.13 76.732,23.059 75.575,24.216
NetR59_1: R59.1 TP2.1 | length 1.4
  Top Layer w0.4: R59.1 TP2.1
NetU4_4: U4.4 U6.2 | length 14
  Top Layer w0.5: U4.4 v1(62.146,53.266) ; v1(72.612,54.241) U6.2
  Bottom Layer w0.5: v1(62.146,53.266) 71.638,53.266 v1(72.612,54.241)
NetU8_2: U8.2 U8.5 | length 6.9
  Top Layer w0.5: U8.5 72.922,28.038 73.401,28.517 76.147,28.517 76.732,27.931 U8.2
POWER: C32.1 R43.1 S1.9 | length 78.1
  Top Layer w0.5: C32.1 R43.1 34.326,43.815 39.421,38.72 71.514,38.72 v1(75.725,34.508) ; S1.9 v1(83.199,10.951)
  Bottom Layer w0.5: v1(75.725,34.508) 79.939,30.295 79.939,14.211 v1(83.199,10.951)
PP: R66.2 S1.6 | length 5.2
  Top Layer w0.5: R66.2 80.199,14.202 S1.6
RA0: DIS2.11 U7.19 | length 21.4
  Top Layer w0.4: U7.19 99.51,56.05 100.19,55.369 100.19,47.264 100.814,46.641 DIS2.11
RA1: DIS2.12 U7.20 | length 26.8
  Top Layer w0.4: U7.20 99.408,56.85 v1(100.061,57.503) ; v1(99.045,54.844) 99.045,45.988 100.932,44.101 DIS2.12
  Bottom Layer w0.4: v1(99.045,54.844) 100.061,55.86 v1(100.061,57.503)
RA2: DIS2.3 U7.21 | length 20.7
  Top Layer w0.4: U7.21 95.666,57.65 v1(96.97,58.953)
  Bottom Layer w0.4: v1(96.97,58.953) 96.97,65.917 98.014,66.961 DIS2.3
RA3: U6.5 U7.22 | length 31.6
  Top Layer w0.4: v1(70.072,48.467) U6.5 ; v1(90.706,58.45) U7.22
  Bottom Layer w0.4: v1(70.072,48.467) 75.378,48.467 81.309,54.398 81.309,57.266 81.898,57.855 82.73,57.855 84.33,56.255 90.116,56.255 90.706,56.846 v1(90.706,58.45)
RA4: DIS2.13 U7.23 | length 35.3
  Top Layer w0.4: U7.23@90.39,60.15 v1(100.173,60.15) ; v1(97.968,53.464) 97.968,43.141 99.548,41.561 DIS2.13
  Bottom Layer w0.4: v1(97.968,53.464) 97.968,56.947 100.173,59.152 v1(100.173,60.15)
RA5: C42.2 R62.1 R63.1 R65.2 R66.1 R68.1 U7.24 | length 66.8
  Top Layer w0.4: v1(76.197,46.833) v1(76.197,50.97) ; v1(89.588,57.399) 89.588,60.149 U7.24
  Top Layer w0.5: R62.1 R63.1 R66.1 R68.1 C42.2 R65.2 v1(83.984,18.996)
  Bottom Layer w0.4: v1(76.197,46.833) 82.53,40.5 82.53,20.45 v1(83.984,18.996) ; v1(76.197,50.97) 80.604,55.377 80.604,57.558 81.606,58.56 83.022,58.56 84.197,57.385 89.574,57.385 v1(89.588,57.399)
RB0: DIS2.10 U7.8 | length 20.4
  Top Layer w0.4: U7.8 87.989,46.768 v1(88.61,46.147)
  Bottom Layer w0.4: v1(88.61,46.147) 89.18,46.717 97.888,46.717 100.352,49.181 DIS2.10
RB2: U3.6 U7.10 | length 79.6
  Top Layer w0.4: U3.6 32.375,29.845 31.633,30.587 31.633,34.938 33.01,36.314 v1(39.484,36.314) ; v1(79.929,41.138) 80.805,42.014 v1(80.805,48.097) ; U7.10 v1(89.589,51.357)
  Bottom Layer w0.4: v1(39.484,36.314) 75.105,36.314 v1(79.929,41.138) ; v1(80.805,48.097) 80.805,50.446 81.716,51.357 v1(89.589,51.357)
RB4: DIS2.1 U7.14 | length 32.8
  Top Layer w0.4: U7.14 94.107,52.05 v1(94.628,51.529)
  Bottom Layer w0.4: v1(94.628,51.529) 94.628,70.901 95.768,72.041 DIS2.1
RB5: DIS2.2 U7.15 | length 28.6
  Top Layer w0.4: U7.15 v1(95.646,52.85)
  Bottom Layer w0.4: v1(95.646,52.85) 95.646,68.076 97.071,69.501 DIS2.2
RC0: R32.2 U7.32 | length 11.7
  Top Layer w0.4: R32.2 82.791,61.9 83.189,61.502 U7.32
RC1: R31.2 U7.35 | length 8.7
  Top Layer w0.4: R31.2 76.843,60.094 79.286,57.65 U7.35
RC2: R36.2 R37.2 U7.36 U9.1 | length 52.4
  Top Layer w0.4: U7.36 v1(82.314,56.85)
  Top Layer w0.5: U9.1 v1(91.928,24.661) R37.2 R36.2
  Bottom Layer w0.4: v1(82.314,56.85) 82.314,54.373 77.213,49.272 77.213,47.719 82.203,42.729 89.201,42.729 90.104,41.826 90.104,26.485 v1(91.928,24.661)
RC3: U6.7 U7.37 | length 11.5
  Top Layer w0.4: U6.7 72.612,51.546 77.117,56.05 U7.37
RC4: U6.6 U7.42 | length 11.4
  Top Layer w0.4: v1(71.341,52.05) 71.342,52.048 U6.6 ; v1(75.017,52.05) U7.42
  Bottom Layer w0.4: v1(71.341,52.05) v1@75.016,52.05
RC6: DIS2.17 U7.44 | length 41.9
  Top Layer w0.4: v1(78.402,48.702) 78.402,50 78.852,50.45 U7.44
  Bottom Layer w0.4: v1(78.402,48.702) 78.402,47.591 82.559,43.434 99.393,43.434 99.987,42.84 99.987,36.289 DIS2.17
RC7: DIS2.5 U7.1 | length 30.6
  Top Layer w0.4: U7.1 v1(82.389,50.241)
  Bottom Layer w0.4: v1(82.389,50.241) 96.321,50.241 102.287,56.206 102.287,59.293 DIS2.5
RD0: DIS2.4 U7.38 | length 34.4
  Top Layer w0.4: U7.38 v1(85.189,55.25) ; v1(91.872,65.768) 102.273,65.768 103.62,64.421 DIS2.4 DIS2.4
  Bottom Layer w0.4: v1(85.189,55.25) 90.432,55.25 91.872,56.69 v1(91.872,65.768)
RD1: U4.10 U4.11 U7.39 | length 34.3
  Top Layer w0.4: v1(78.181,54.915) 78.646,54.45 U7.39
  Top Layer w0.5: U4.11 56.256,55.806 56.632,56.182 v1(56.632,57.076) U4.10
  Bottom Layer w0.4: v1(56.632,57.076) 56.632,58.958 57.175,59.502 76.563,59.502 78.181,57.884 v1(78.181,54.915)
RD2: U4.9 U7.40 | length 29.9
  Top Layer w0.4: v1(77.064,53.65) U7.40
  Top Layer w0.5: U4.9 v1(57.714,58.346)
  Bottom Layer w0.4: v1(57.714,58.346) 76.251,58.346 77.064,57.534 v1(77.064,53.65)
RD3: DIS2.16 U7.41 | length 42.1
  Top Layer w0.4: U7.41 v1(82.212,52.85)
  Bottom Layer w0.4: v1(82.212,52.85) 79.407,50.045 79.407,47.583 82.851,44.139 99.793,44.139 100.692,43.24 100.692,38.124 DIS2.16
RD4: DIS2.6 U7.2 | length 32.4
  Top Layer w0.4: v1(82.718,46.434) 83.189,46.905 U7.2
  Bottom Layer w0.4: v1(82.718,46.434) 82.718,49.012 83.242,49.536 96.613,49.536 102.992,55.914 102.992,57.458 DIS2.6
RD5: DIS2.7 U7.3 | length 30
  Top Layer w0.4: v1(83.989,45.706) U7.3
  Bottom Layer w0.4: v1(83.989,45.706) 83.989,48.193 84.627,48.831 96.905,48.831 DIS2.7
RD6: DIS2.8 U7.4 | length 26.5
  Top Layer w0.4: U7.4 84.789,46.681 v1(85.334,46.137)
  Bottom Layer w0.4: v1(85.334,46.137) 85.334,47.508 85.952,48.126 97.304,48.126 103.439,54.261 DIS2.8
RD7: DIS2.9 U7.5 | length 26.1
  Top Layer w0.4: U7.5 85.589,47.545 86.413,46.721 v1(86.413,45.227)
  Bottom Layer w0.4: v1(86.413,45.227) 86.413,47.038 86.796,47.421 97.596,47.421 101.895,51.721 DIS2.9
RE0: U7.25 U17.6 | length 116.9
  Top Layer w0.4: v1(27.653,34.887) 27.653,37.859 28.834,39.04 v1(35.212,39.04) ; v1(36.137,45.24) v1(36.137,60.249) ; v1(88.323,58.39) 88.789,58.855 U7.25
  Top Layer w0.6: U17.6 v1(20.233,9.45)
  Bottom Layer w0.4: v1(20.233,9.45) 20.233,13.133 27.653,20.554 v1(27.653,34.887) ; v1(35.212,39.04) 36.137,39.964 v1(36.137,45.24) ; v1(36.137,60.249) 86.464,60.249 v1(88.323,58.39)
RE1: DIS2.14 U7.26 | length 39.8
  Top Layer w0.4: U7.26 87.989,61.535 88.43,61.976 102.131,61.976 102.898,61.209 v1(102.898,47.879)
  Bottom Layer w0.4: v1(102.898,47.879) 102.898,40.998 DIS2.14
RE2: DIS2.15 U7.27 | length 44.5
  Top Layer w0.4: U7.27 87.189,62.026 88.229,63.066 v1(101.397,63.066) ; v1(101.397,47.859) v1(101.397,60.836)
  Bottom Layer w0.4: v1(101.397,47.859) 101.397,39.96 DIS2.15 ; v1(101.397,60.836) v1(101.397,63.066)
RE3: J1.5 RP1.5 RP1.6 U7.18 | length 38.7
  Top Layer w0.4: U7.18 96.233,55.25 v1(96.789,54.694) 96.789,46.154 ; RP1.6 95.976,45.883 96.248,46.154 96.789,46.154 ; RP1.5 96.789,46.154
  Bottom Layer w0.4: v1(96.789,54.694) 96.789,57.056 98.87,59.137 98.87,62.987 100.086,64.204 102.413,64.204 103.464,63.152 J1.5@110.167,63.152
SET: R68.2 S1.7 | length 5.5
  Top Layer w0.5: S1.7 81.199,13.384 R68.2
UP: R62.2 S1.4 | length 5.9
  Top Layer w0.5: R62.2 78.199,12.587 S1.4
VBT: BT1.1 D1.1 DC1.1 | length 21.4
  Top Layer w1.2: BT1.1 10.655,22.723 12.619,24.686 D1.1 9.8,35.598 DC1.1
VBT1: C34.2 Q2.3 Q3.2 RP1.1 U15.8 | length 115.6
  Top Layer w0.4: v1(94.376,40.483) RP1.1
  Top Layer w0.5: Q2.3 29.965,49.615 39.901,39.68 72.296,39.68 76.736,35.24 v1@93.97,35.24
  Top Layer w0.6: C34.2 U15.8 ; Q2.3 C34.2@29.038,52.062 ; v1(109.576,11.741) Q3.2
  Bottom Layer w0.4: v1@93.97,35.24 93.97,34.478 109.576,18.872 v1(109.576,11.741) ; v1(94.376,35.24) v1(94.376,40.483)
VDD: C5.2 C35.1 Q6.2 R7.1 R9.2 R14.1 R17.1 R46.1 R57.2 U1.5 U2.8 U3.16 U4.16 U5.8 U15.1 U15.2 U17.1 U17.5 | length 218.8
  Top Layer w0.5: U3.16 30.196,23.495 30.704,22.987 v1(30.704,22.319)
  Top Layer w0.6: R9.2 15.301,8.923 16.279,8.923 16.612,8.59 U17.1 18.374,8.59 19.324,7.64 U17.5 22.343,7.64 R7.1 v1(22.394,8.675) ; v1(24.096,27.179) U2.8 24.096,24.39 25.152,23.334 R14.1 25.721,23.495 U3.16 ; R17.1 v1(25.403,36.137) ; U15.2 27.767,62.73 28.169,63.132 29.037,63.132 ; v1(30.282,64.419) R57.2 29.037,63.132 ; C35.1 v1(29.891,61.318) U15.1 29.037,63.132 ; U5.8 v1(42.156,48.331) 52.54,48.331 53.665,49.456 U4.16 ; U1.5 v1(44.461,18.645) 44.461,19.055 C5.2 ; Q6.2 v1(74.168,33.177) ; v1(77.635,64.699) R46.1
  Bottom Layer w0.6: v1(22.394,8.675) 22.394,14.157 30.556,22.319 v1(30.704,22.319) 40.787,22.319 v1(44.461,18.645) 58.994,33.177 v1(74.168,33.177) ; v1(24.096,27.179) 25.403,28.486 v1(25.403,36.137) 31.544,36.137 32.382,36.975 32.382,48.339 ; v1(29.891,61.318) 31.608,61.318 32.382,60.543 32.382,48.339 ; v1(30.282,64.419) 31.615,64.419 31.895,64.699 v1(77.635,64.699) ; v1(42.156,48.331) 32.39,48.331 32.382,48.339
VDD1: C23.1 C24.1 C25.1 C27.1 C28.1 C30.1 C36.2 J1.1 Q5.2 R39.1 R46.2 R65.1 RP1.3 RP1.4 S1.3 U6.8 U7.7 U7.28 U8.9 U8.14 U9.14 | length 192.2
  Top Layer w0.4: C25.1@86.389,64.693 C25.1 101.707,64.699 103.258,63.148 106.166,63.148 106.906,62.408 106.906,56.215 J1.1 ; Q5.2 88.732,38.633 96.23,38.633 96.789,39.192 96.789,41.438 ; RP1.3 95.976,41.737 96.276,41.438 96.789,41.438 ; RP1.4 96.789,41.438
  Top Layer w0.45: C25.1@86.389,64.693 U7.28 86.389,57.814 87.189,57.014 U7.7 87.189,46.171 87.592,45.768 C28.1
  Top Layer w0.5: v1(71.652,19.204) U8.9 ; v1(77.199,7.105) S1.3 ; v1(78.003,19.205) 78.002,19.206 U8.14 78.002,22.082 78.565,22.644 C30.1 ; U9.14 C30.1 ; R65.1 85.66,19.755 84.075,21.34 C30.1 ; Q5.2 84.078,39.796 v1(84.077,39.797) 84.077,43.203 84.679,43.805 C27.1 C28.1 ; v1(107.575,7.832) R39.1
  Top Layer w0.6: U6.8 73.887,50.01 C23.1 73.887,42.243 76.333,39.797 v1(84.077,39.797)
  Top Layer w0.8: R46.2 C36.2 C24.1 C25.1
  Bottom Layer w0.5: v1(71.652,19.204) v1(71.652,19.204) v1(78.003,19.205) 78.003,7.91 v1(77.199,7.105) ; v1(84.077,39.797) v1(84.077,23.711) 84.077,21.42 85.032,20.465 94.943,20.465 v1(107.575,7.832)
VEE: C3.1 C13.1 C15.1 C21.2 C22.2 J2.1 J2.4 R1.1 R2.1 R3.1 R10.1 R15.1 R20.1 R33.2 R58.1 U3.1 U3.3 U3.13 U5.3 U5.5 U6.1 U10.1 U10.2 U16.1 U16.8 | length 230.8
  Top Layer w0.5: C13.1 27.112,26.899 27.518,27.305 U3.13 v1(30.226,27.305) ; R15.1 31.374,21.123 31.938,21.687 31.938,23.495 ; U3.3 v1(32.395,26.035) 31.938,25.578 31.938,23.495 ; R20.1 39.74,23.496 C15.1 39.741,22.355 38.593,21.206 ; 40.922,8.105 40.193,8.834 40.193,14.244 38.593,15.845 38.593,21.206 ; 31.938,23.495 U3.1 36.304,23.495 38.593,21.206
  Top Layer w0.6: U16.1 U16.8 v1(18.069,62.047) 18.069,63.407 U10.2 U10.1 18.067,67.268 R58.1 ; v1(34.795,46.713) v1(34.795,50.47) ; U5.5 v1(37.477,50.464) 38.747,51.734 U5.3 ; C21.2 66.571,51.412 v1(66.571,56.451) ; v1@65.293,62.682 v1(65.296,62.685) ; R33.2 73.882,57.457 U6.1 v1(74.699,55.756)
  Top Layer w0.8: R10.1 18.65,2.225 33.345,2.225 ; J2.1 33.302,2.268 33.345,2.225 ; R1.1 40.922,8.105 J2.4 40.922,2.232 40.93,2.225 ; R2.1 C3.1 ; R3.1 C3.1 ; v1@65.293,62.682 C22.2 v1(66.571,56.451) ; 33.345,2.225 40.93,2.225 ; 40.93,2.225 46.393,2.225 47.113,2.945 C3.1
  Bottom Layer w0.5: v1(30.226,27.305) 31.125,27.305 v1(32.395,26.035)
  Bottom Layer w0.6: v1(30.226,27.305) 30.226,33.266 33.703,36.744 33.703,45.621 v1(34.795,46.713) ; 33.63,62.685 33.703,62.611 ; 34.795,62.611 v1(34.795,50.47) 37.47,50.47 v1(37.477,50.464)
  Bottom Layer w0.8: v1(18.069,62.047) 18.707,62.685 33.63,62.685 v1(65.296,62.685) ; v1(66.571,56.451) 67.285,57.165 73.289,57.165 v1(74.699,55.756)
pads on no net: D3.1 MK1.1 MK2.1 MK3.1 MK4.1 S1.1 S1.11 S1.12 U7.12 U7.13 U7.30 U7.31 U7.33 U7.34 U7.43 U8.12 U9.6 U9.8 U9.9 U9.10 U9.11 U14.13 U15.3 U15.5 U16.2 U16.3 U16.4 U16.5 U16.7

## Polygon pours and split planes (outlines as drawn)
GND on Bottom Layer "Bottom Layer-No Net" (solid, remove dead copper, pour order 2): 11.5,0 108.5,0 122,13.5 122,34.303 121.557,43.706 120.19,54.343 118.689,61.488 116.434,69.858 115.06,74 7.045,74 5.763,70.162 4.389,65.461 3.129,60.462 1.974,54.948 1.5,51.917 1.5,10

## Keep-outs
Keep-Out Layer:
  lines w0.2: 1.501,52.065 cw(c123.242,32.89) 7.057,73.996 ; 7.045,74 115.06,74 ; 11.5,0 108.5,0 122,13.5 122,34.303 ccw(c-3.242,32.868) 115.061,74.001
  lines w0.203: 1.5,52.065 1.5,10 11.5,0

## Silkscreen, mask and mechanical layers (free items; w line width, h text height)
Top Overlay:
  circle w0.127: c93,13.3 r3
  circle w0.2: c60,16.5 r5.5
  circle w0.127: c27,13.3 r3
  text "GT990_V1.1" at 44.651,66.832 h2
  text "BAT-" at 9.952,24.689 h1
  text "BAT+" at 9.936,22.207 h1
Bottom Overlay:
  lines w0.2: 104.725,30.765 104.725,23.72 16.025,23.72 16.025,35.22 12.525,35.22 12.525,68.22 16.025,68.22 16.025,79.72 104.725,79.72 104.725,72.675
Mechanical 3:
  circle w0.1: c16.025,29.47 r0.05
